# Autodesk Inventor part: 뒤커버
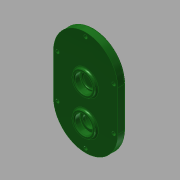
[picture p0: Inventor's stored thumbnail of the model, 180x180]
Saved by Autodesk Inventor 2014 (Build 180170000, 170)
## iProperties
Created: 2016-12
Part Number: 뒤커버
Material: Aluminum 6061
Document SubType Name: Modeling
Designer: mduedu
Density: 1 g/cm^3
Appearance: Smooth - Dark Forest Green
Mass: 87.2434 g
Surface Area: 240.701 cm^2
Volume: 87.2434 cm^3
Author: mduedu
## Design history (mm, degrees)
sketch "스케치1"
  geometry: L1 (40, -25)-(40, 25); L2 (-40, 25)-(-40, -25); L3 (-40, -25)-(40, 25); L4 (40, -25)-(-40, 25); A1 r 40 centre (0, 25) between (40, 25) and (-40, 25); A2 r 40 centre (0, -25) between (-40, -25) and (40, -25); 1 further point
  constraints: 8 end point, 4 point on circle, 4 tangent, 2 centre point, 2 midpoint, 1 parallel, 1 vertical
  dimensions: "d0" = 130 dimension on A2 A1; "d2" = 80 distance between parallel lines of L1 L2
extrude "돌출1" new body sketch "스케치1" distance "d3" = 10; taper "d4" = 0 deg
sketch "스케치2"
  geometry: C1 r 14 at (0, 11); 1 further point
  constraints: 1 centre point, 1 vertical alignment
  dimensions: "d5" = 28 diameter of C1; "d6" = 11 distance of C1.centre point (0, 0)
extrude "돌출2" join sketch "스케치2" distance "d7" = 3; taper "d8" = 0 deg
sketch "스케치3"
  geometry: C1 r 14 at (0, -33.1); C2 r 14 at (0, 11) reference; 1 further point
  constraints: 1 centre point, 1 vertical alignment
  dimensions: "d9" = 28 diameter of C1; "d69" = 44.1 distance of C1.centre C2.centre
extrude "돌출3" join sketch "스케치3" distance "d11" = 3; taper "d12" = 0 deg
hole "구멍1" diameter "d15" = 22; stored, may be unused: countersink angle "d19" = 90 deg, drill point angle "d21" = 0 deg; dims "d13" = 10, "d14" = 10, "d16" = 6, "d17" = 4, "d18" = 2, "d20" = 7
hole "구멍2" diameter "d24" = 18; stored, may be unused: countersink angle "d28" = 90 deg, drill point angle "d30" = 0 deg; dims "d22" = 10, "d23" = 10, "d25" = 6, "d26" = 4, "d27" = 2, "d29" = 1
hole "구멍3" diameter "d33" = 22; stored, may be unused: countersink angle "d37" = 90 deg, drill point angle "d39" = 0 deg; dims "d31" = 10, "d32" = 10, "d34" = 6, "d35" = 4, "d36" = 2, "d38" = 7
sketch "스케치4"
  geometry: C1 r 14 at (0, -33.1) reference; C2 r 18 at (0, -33.1); 1 further point
  constraints: 1 centre point, 1 coincident
  dimensions: "d40" = 36 diameter of C2
extrude "돌출4" join sketch "스케치4" distance "d41" = 4; taper "d42" = 0 deg
hole "구멍4" diameter "d45" = 22; stored, may be unused: countersink angle "d49" = 90 deg, drill point angle "d51" = 0 deg; dims "d43" = 10, "d44" = 10, "d46" = 6, "d47" = 4, "d48" = 2, "d50" = 7
hole "구멍5" diameter "d54" = 15; stored, may be unused: countersink angle "d58" = 90 deg, drill point angle "d60" = 0 deg; dims "d52" = 10, "d53" = 10, "d55" = 6, "d56" = 4, "d57" = 2, "d59" = 7
fillet "모깎기1" dims "d61" = 0.3
fillet "모깎기2" dims "d62" = 2
chamfer "모따기1" distance "d63" = 1; stored, may be unused: second distance "d64" = 2, angle "d65" = 45 deg
fillet "모깎기3" dims "d66" = 2
fillet "모깎기4" dims "d67" = 2
fillet "모깎기5" dims "d68" = 2
sketch "스케치5"
  geometry: L1 (-40, 25)-(-40, -25) reference; L2 (40, -25)-(40, 25) reference; L3 (35, 25)-(35, -25); L4 (-35, -25)-(-35, 25); A1 r 40 centre (0, 25) between (40, 25) and (-40, 25) reference; A2 r 40 centre (0, -25) between (-40, -25) and (40, -25) reference; A3 r 35 centre (0, 25) between (35, 25) and (-35, 25); A4 r 35 centre (0, -25) between (-35, -25) and (35, -25); 2 further points
  constraints: 5 point on circle, 4 end point, 2 centre point, 1 vertical alignment, 3 other
  dimensions: "d70" = 5 distance between parallel lines of L2 L3
sketch "스케치6"
  geometry: 1 further point
hole "구멍6" sketch "스케치6" at (0, 60) diameter "d71" = 4.5; stored, may be unused: countersink angle "d75" = 90 deg, drill point angle "d77" = 0 deg; dims "d72" = 6, "d73" = 8, "d74" = 4.6, "d76" = 8
node "솔리드1"
pattern_linear "직사각형 패턴1"
